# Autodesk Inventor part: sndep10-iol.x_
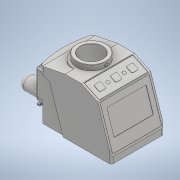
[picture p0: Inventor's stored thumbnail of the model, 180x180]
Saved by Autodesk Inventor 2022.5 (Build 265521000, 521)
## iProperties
Created: 2019-12
Part Number: sndep10-iol.x_
Material: 一般
Document SubType Name: Modeling
Designer: ImaoCorp
Density: 1 g/cm^3
Appearance: 既定
Sending System: SOLIDWORKS 2018-2018316
MC: AMD64
MC_MODEL: Intel64 Family 6 Model 60 Stepping 3, GenuineIntel
OS: Windows_NT
FRU: Parasolid Version 30.0, build 310,  6- 8-2018
FORMAT: text
GUISE: transmit
KEY: sndep10-iol
FILE: sndep10-iol.x_t
DATE: Wed Dec 11 13:18:41 2019
Author: ImaoCorp
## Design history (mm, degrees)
feature "Base1"
node "ソリッド1"
